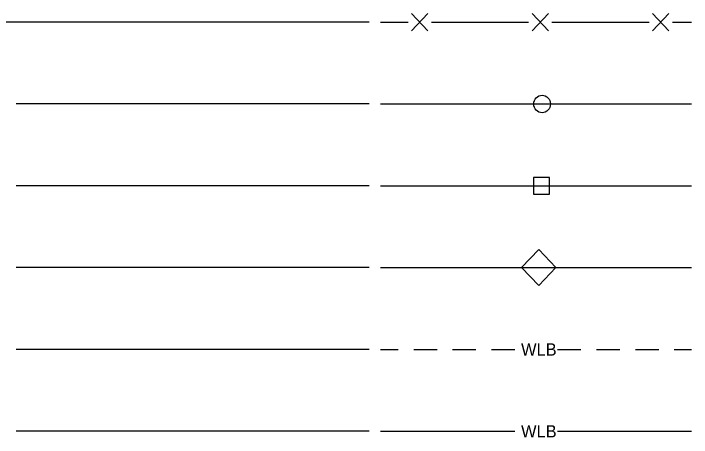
# Model space of a CAD drawing. Extents: x 2025847 to 2026166, y 840763 to 840870.
# Drawn here: x 2026039.91 to 2026054.27, y 840836.9 to 840845.88 of the extents above; entities that cross this region are included whole.
import ezdxf

# ---------------------------------------------------------------- set-up
doc = ezdxf.new("R2010")
doc.units = 0
doc.layers.add('Sheet_Symbology', color=7, linetype='Continuous')

msp = doc.modelspace()

# ---------------------------------------------------------------- linework, layer by layer
at = {"layer": 'Sheet_Symbology'}
for p, q in [((2026048.341, 840845.514), (2026048.687, 840845.878)), ((2026048.687, 840845.514), (2026048.341, 840845.878)), ((2026050.893, 840845.514), (2026051.238, 840845.878)), ((2026051.238, 840845.514), (2026050.893, 840845.878)), ((2026053.445, 840845.514), (2026053.79, 840845.878)), ((2026053.79, 840845.514), (2026053.445, 840845.878)), ((2026047.446, 840845.696), (2026035.501, 840845.696)), ((2026047.682, 840845.696), (2026048.267, 840845.696)), ((2026048.761, 840845.696), (2026049.79, 840845.696)), ((2026049.79, 840845.696), (2026050.819, 840845.696)), ((2026051.313, 840845.696), (2026052.342, 840845.696)), ((2026052.342, 840845.696), (2026053.37, 840845.696)), ((2026053.864, 840845.696), (2026054.268, 840845.696)), ((2026047.446, 840843.963), (2026039.968, 840843.963)), ((2026047.682, 840843.963), (2026054.268, 840843.963)), ((2026047.682, 840843.963), (2026054.268, 840843.963)), ((2026047.446, 840842.23), (2026039.968, 840842.23)), ((2026047.682, 840842.23), (2026054.268, 840842.23)), ((2026047.682, 840842.23), (2026054.268, 840842.23)), ((2026047.446, 840840.497), (2026039.968, 840840.497)), ((2026047.682, 840840.497), (2026054.268, 840840.497)), ((2026047.682, 840840.497), (2026054.268, 840840.497)), ((2026047.446, 840838.764), (2026039.968, 840838.764)), ((2026047.682, 840838.764), (2026048.059, 840838.764)), ((2026048.388, 840838.764), (2026048.882, 840838.764)), ((2026049.211, 840838.764), (2026049.705, 840838.764)), ((2026050.035, 840838.764), (2026050.529, 840838.764)), ((2026051.434, 840838.764), (2026051.928, 840838.764)), ((2026052.257, 840838.764), (2026052.751, 840838.764)), ((2026053.08, 840838.764), (2026053.574, 840838.764)), ((2026053.903, 840838.764), (2026054.268, 840838.764)), ((2026047.446, 840837.031), (2026039.968, 840837.031)), ((2026047.446, 840837.031), (2026039.968, 840837.031)), ((2026047.682, 840837.031), (2026050.529, 840837.031)), ((2026051.434, 840837.031), (2026054.268, 840837.031))]:
    msp.add_line(p, q, dxfattribs=at)
for points in [[(2026050.924, 840842.052), (2026051.261, 840842.052), (2026051.261, 840842.408), (2026050.924, 840842.408)], [(2026051.033, 840840.116), (2026051.395, 840840.497), (2026051.033, 840840.883), (2026050.67, 840840.497)]]:
    msp.add_lwpolyline(points, close=True, dxfattribs=at)
msp.add_ellipse((2026051.105, 840843.963), major_axis=(0, 0.186), ratio=0.95, dxfattribs=at)

# ---------------------------------------------------------------- texts
for p in [(2026050.66, 840838.634), (2026050.66, 840836.901)]:
    msp.add_text('WLB', height=0.2599, dxfattribs=at).set_placement(p)

doc.saveas('drawing.dxf')
